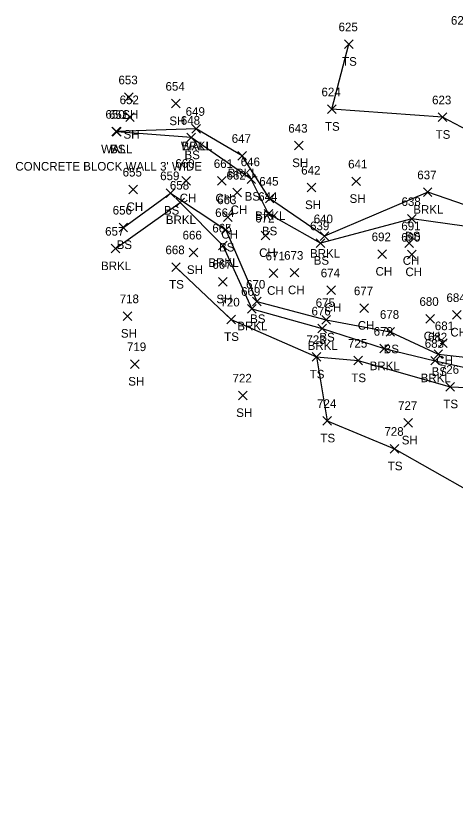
# Model space of a CAD drawing. Extents: x 1638705 to 1644019, y 630225 to 637423.
# Drawn here: x 1643714 to 1643815.9, y 636980.7 to 637165.6 of the extents above; entities that cross this region are included whole.
import ezdxf

# ---------------------------------------------------------------- set-up
doc = ezdxf.new("R2010")
doc.units = 0
for name, color, linetype in [('L_A', 7, 'Continuous'), ('L_C', 7, 'Continuous'), ('L_I', 7, 'Continuous'), ('L_TIC', 7, 'Continuous'), ('LAWE', 7, 'Continuous'), ('LELB', 7, 'Continuous'), ('LW', 7, 'Continuous')]:
    doc.layers.add(name, color=color, linetype=linetype)

msp = doc.modelspace()

# ---------------------------------------------------------------- linework, layer by layer
at = {"layer": 'L_TIC'}
for points in [[(1643790.25, 637158.07), (1643792.25, 637160.07)], [(1643792.25, 637158.07), (1643790.25, 637160.07)], [(1643739.18, 637145.77), (1643741.18, 637147.77)], [(1643741.18, 637145.77), (1643739.18, 637147.77)], [(1643750.1, 637144.29), (1643752.1, 637146.29)], [(1643752.1, 637144.29), (1643750.1, 637146.29)], [(1643786.29, 637142.99), (1643788.29, 637144.99)], [(1643788.29, 637142.99), (1643786.29, 637144.99)], [(1643739.45, 637141.16), (1643741.45, 637143.16)], [(1643741.45, 637141.16), (1643739.45, 637143.16)], [(1643811.95, 637141.13), (1643813.95, 637143.13)], [(1643813.95, 637141.13), (1643811.95, 637143.13)], [(1643736.25, 637137.79), (1643738.25, 637139.79)], [(1643738.25, 637137.79), (1643736.25, 637139.79)], [(1643736.4, 637137.75), (1643738.4, 637139.75)], [(1643738.4, 637137.75), (1643736.4, 637139.75)], [(1643754.78, 637138.46), (1643756.78, 637140.46)], [(1643756.78, 637138.46), (1643754.78, 637140.46)], [(1643754.78, 637138.46), (1643756.78, 637140.46)], [(1643756.78, 637138.46), (1643754.78, 637140.46)], [(1643753.65, 637136.4), (1643755.65, 637138.4)], [(1643755.65, 637136.4), (1643753.65, 637138.4)], [(1643778.59, 637134.56), (1643780.59, 637136.56)], [(1643780.59, 637134.56), (1643778.59, 637136.56)], [(1643765.46, 637132.19), (1643767.46, 637134.19)], [(1643767.46, 637132.19), (1643765.46, 637134.19)], [(1643752.5, 637126.41), (1643754.5, 637128.41)], [(1643754.5, 637126.41), (1643752.5, 637128.41)], [(1643767.6, 637126.78), (1643769.6, 637128.78)], [(1643769.6, 637126.78), (1643767.6, 637128.78)], [(1643760.78, 637126.36), (1643762.78, 637128.36)], [(1643762.78, 637126.36), (1643760.78, 637128.36)], [(1643781.58, 637124.82), (1643783.58, 637126.82)], [(1643783.58, 637124.82), (1643781.58, 637126.82)], [(1643791.9, 637126.26), (1643793.9, 637128.26)], [(1643793.9, 637126.26), (1643791.9, 637128.26)], [(1643740.15, 637124.38), (1643742.15, 637126.38)], [(1643742.15, 637124.38), (1643740.15, 637126.38)], [(1643748.87, 637123.53), (1643750.87, 637125.53)], [(1643750.87, 637123.53), (1643748.87, 637125.53)], [(1643764.3, 637123.67), (1643766.3, 637125.67)], [(1643766.3, 637123.67), (1643764.3, 637125.67)], [(1643808.52, 637123.74), (1643810.52, 637125.74)], [(1643810.52, 637123.74), (1643808.52, 637125.74)], [(1643751.11, 637121.35), (1643753.11, 637123.35)], [(1643753.11, 637121.35), (1643751.11, 637123.35)], [(1643771.85, 637122.27), (1643773.85, 637124.27)], [(1643773.85, 637122.27), (1643771.85, 637124.27)], [(1643762.14, 637117.97), (1643764.14, 637119.97)], [(1643764.14, 637117.97), (1643762.14, 637119.97)], [(1643771.61, 637118.73), (1643773.61, 637120.73)], [(1643773.61, 637118.73), (1643771.61, 637120.73)], [(1643804.86, 637117.55), (1643806.86, 637119.55)], [(1643806.86, 637117.55), (1643804.86, 637119.55)], [(1643737.9, 637115.56), (1643739.9, 637117.56)], [(1643739.9, 637115.56), (1643737.9, 637117.56)], [(1643761.67, 637114.99), (1643763.67, 637116.99)], [(1643763.67, 637114.99), (1643761.67, 637116.99)], [(1643770.92, 637113.71), (1643772.92, 637115.71)], [(1643772.92, 637113.71), (1643770.92, 637115.71)], [(1643784.58, 637113.55), (1643786.58, 637115.55)], [(1643786.58, 637113.55), (1643784.58, 637115.55)], [(1643783.63, 637111.92), (1643785.63, 637113.92)], [(1643785.63, 637111.92), (1643783.63, 637113.92)], [(1643783.63, 637111.92), (1643785.63, 637113.92)], [(1643785.63, 637111.92), (1643783.63, 637113.92)], [(1643804.25, 637111.9), (1643806.25, 637113.9)], [(1643806.25, 637111.9), (1643804.25, 637113.9)], [(1643736.09, 637110.66), (1643738.09, 637112.66)], [(1643738.09, 637110.66), (1643736.09, 637112.66)], [(1643754.16, 637109.78), (1643756.16, 637111.78)], [(1643756.16, 637109.78), (1643754.16, 637111.78)], [(1643761, 637111.4), (1643763, 637113.4)], [(1643763, 637111.4), (1643761, 637113.4)], [(1643797.93, 637109.38), (1643799.93, 637111.38)], [(1643799.93, 637109.38), (1643797.93, 637111.38)], [(1643804.87, 637109.27), (1643806.87, 637111.27)], [(1643806.87, 637109.27), (1643804.87, 637111.27)], [(1643750.12, 637106.36), (1643752.12, 637108.36)], [(1643752.12, 637106.36), (1643750.12, 637108.36)], [(1643772.77, 637104.94), (1643774.77, 637106.94)], [(1643774.77, 637104.94), (1643772.77, 637106.94)], [(1643777.62, 637105.08), (1643779.62, 637107.08)], [(1643779.62, 637105.08), (1643777.62, 637107.08)], [(1643761.01, 637102.98), (1643763.01, 637104.98)], [(1643763.01, 637102.98), (1643761.01, 637104.98)], [(1643786.12, 637101), (1643788.12, 637103)], [(1643788.12, 637101), (1643786.12, 637103)], [(1643768.88, 637098.38), (1643770.88, 637100.38)], [(1643770.88, 637098.38), (1643768.88, 637100.38)], [(1643793.81, 637096.85), (1643795.81, 637098.85)], [(1643795.81, 637096.85), (1643793.81, 637098.85)], [(1643738.85, 637095), (1643740.85, 637097)], [(1643740.85, 637095), (1643738.85, 637097)], [(1643767.69, 637096.71), (1643769.69, 637098.71)], [(1643769.69, 637096.71), (1643767.69, 637098.71)], [(1643815.29, 637095.27), (1643817.29, 637097.27)], [(1643817.29, 637095.27), (1643815.29, 637097.27)], [(1643762.89, 637094.24), (1643764.89, 637096.24)], [(1643764.89, 637094.24), (1643762.89, 637096.24)], [(1643784.95, 637094.12), (1643786.95, 637096.12)], [(1643786.95, 637094.12), (1643784.95, 637096.12)], [(1643809.11, 637094.38), (1643811.11, 637096.38)], [(1643811.11, 637094.38), (1643809.11, 637096.38)], [(1643784.02, 637092.15), (1643786.02, 637094.15)], [(1643786.02, 637092.15), (1643784.02, 637094.15)], [(1643799.85, 637091.37), (1643801.85, 637093.37)], [(1643801.85, 637091.37), (1643799.85, 637093.37)], [(1643812.02, 637088.74), (1643814.02, 637090.74)], [(1643814.02, 637088.74), (1643812.02, 637090.74)], [(1643798.41, 637087.46), (1643800.41, 637089.46)], [(1643800.41, 637087.46), (1643798.41, 637089.46)], [(1643810.99, 637086.14), (1643812.99, 637088.14)], [(1643812.99, 637086.14), (1643810.99, 637088.14)], [(1643740.54, 637083.88), (1643742.54, 637085.88)], [(1643742.54, 637083.88), (1643740.54, 637085.88)], [(1643782.74, 637085.53), (1643784.74, 637087.53)], [(1643784.74, 637085.53), (1643782.74, 637087.53)], [(1643782.74, 637085.53), (1643784.74, 637087.53)], [(1643784.74, 637085.53), (1643782.74, 637087.53)], [(1643792.4, 637084.68), (1643794.4, 637086.68)], [(1643794.4, 637084.68), (1643792.4, 637086.68)], [(1643810.25, 637084.66), (1643812.25, 637086.66)], [(1643812.25, 637084.66), (1643810.25, 637086.66)], [(1643813.75, 637078.62), (1643815.75, 637080.62)], [(1643815.75, 637078.62), (1643813.75, 637080.62)], [(1643765.6, 637076.6), (1643767.6, 637078.6)], [(1643767.6, 637076.6), (1643765.6, 637078.6)], [(1643785.22, 637070.71), (1643787.22, 637072.71)], [(1643787.22, 637070.71), (1643785.22, 637072.71)], [(1643804.01, 637070.24), (1643806.01, 637072.24)], [(1643806.01, 637070.24), (1643804.01, 637072.24)], [(1643800.85, 637064.24), (1643802.85, 637066.24)], [(1643802.85, 637064.24), (1643800.85, 637066.24)]]:
    msp.add_lwpolyline(points, dxfattribs=at)
at = {"layer": 'LAWE'}
for points in [[(1643849.23, 637088.49), (1643846.16, 637095.89), (1643839.09, 637105.62), (1643831.26, 637117.26), (1643809.52, 637124.74), (1643785.58, 637114.55), (1643772.85, 637123.27), (1643766.46, 637133.19), (1643755.78, 637139.46)], [(1643737.09, 637111.66), (1643752.11, 637122.35), (1643762, 637112.4), (1643768.69, 637097.71), (1643785.02, 637093.15), (1643799.41, 637088.46), (1643811.25, 637085.66), (1643826.85, 637082.12), (1643836.07, 637077.13), (1643839.82, 637076.93), (1643844.4, 637079.83)]]:
    msp.add_lwpolyline(points, dxfattribs=at)
at = {"layer": 'LELB'}
for points in [[(1643855.35, 637129.62), (1643833.54, 637131.3), (1643812.95, 637142.13), (1643787.29, 637143.99), (1643791.25, 637159.07)], [(1643784.63, 637112.92), (1643772.61, 637119.73), (1643768.6, 637127.78), (1643754.65, 637137.4), (1643737.4, 637138.75)], [(1643738.9, 637116.56), (1643749.87, 637124.53), (1643762.67, 637115.99), (1643769.88, 637099.38), (1643785.95, 637095.12), (1643800.85, 637092.37), (1643811.99, 637087.14), (1643823.88, 637085.88), (1643836.52, 637078.79), (1643843.54, 637079.59), (1643841.41, 637081.01), (1643842.47, 637084.34), (1643844.49, 637083.14), (1643845.69, 637086.32), (1643845.17, 637086.3), (1643846.99, 637088.33)], [(1643846.87, 637088.25), (1643845.01, 637094.84), (1643836.71, 637104.68), (1643830.65, 637115.1), (1643805.86, 637118.55), (1643784.63, 637112.92)], [(1643751.12, 637107.36), (1643763.89, 637095.24), (1643783.74, 637086.53), (1643793.4, 637085.68), (1643814.75, 637079.62), (1643828.43, 637079.03), (1643841.12, 637075.24), (1643849.88, 637074.96), (1643851.22, 637078.23), (1643848.74, 637082.34), (1643849.86, 637085.42), (1643854.35, 637085.98), (1643854.22, 637098.04)], [(1643783.74, 637086.53), (1643786.22, 637071.71), (1643801.85, 637065.24), (1643819.33, 637055.34), (1643834.95, 637042.42), (1643840.05, 637008.23), (1643832.85, 636980.73)]]:
    msp.add_lwpolyline(points, dxfattribs=at)
at = {"layer": 'LW'}
msp.add_lwpolyline([(1643755.78, 637139.46), (1643737.25, 637138.79)], dxfattribs=at)

# ---------------------------------------------------------------- texts
at = {"layer": 'L_A'}
for s, p in [('TS', (1643789.66, 637154.07)), ('SH', (1643738.67, 637141.77)), ('SH', (1643749.58, 637140.29)), ('TS', (1643785.69, 637138.99)), ('SH', (1643738.94, 637137.16)), ('TS', (1643811.36, 637137.13)), ('WALL', (1643733.74, 637133.79)), ('WALL', (1643752.26, 637134.46)), ('BRKL', (1643752.42, 637134.46)), ('BS', (1643735.84, 637133.75)), ('BS', (1643753.09, 637132.4)), ('SH', (1643778.08, 637130.56)), ('BRKL', (1643763.11, 637128.19)), ('BS', (1643767.04, 637122.78)), ('CH', (1643751.99, 637122.41)), ('CH', (1643760.27, 637122.36)), ('SH', (1643781.07, 637120.82)), ('SH', (1643791.39, 637122.26)), ('CH', (1643739.64, 637120.38)), ('BS', (1643748.31, 637119.53)), ('CH', (1643763.79, 637119.67)), ('BRKL', (1643806.17, 637119.74)), ('BRKL', (1643748.76, 637117.35)), ('BRKL', (1643769.5, 637118.27)), ('CH', (1643761.63, 637113.97)), ('BS', (1643771.05, 637114.73)), ('BS', (1643804.3, 637113.55)), ('BS', (1643737.34, 637111.56)), ('BS', (1643761.11, 637110.99)), ('CH', (1643770.41, 637109.71)), ('BRKL', (1643782.22, 637109.55)), ('BS', (1643783.07, 637107.92)), ('BS', (1643783.07, 637107.92)), ('CH', (1643803.74, 637107.9)), ('BRKL', (1643733.73, 637106.66)), ('BRKL', (1643758.65, 637107.4)), ('SH', (1643753.65, 637105.78)), ('CH', (1643797.42, 637105.38)), ('CH', (1643804.36, 637105.27)), ('TS', (1643749.53, 637102.36)), ('CH', (1643772.26, 637100.94)), ('CH', (1643777.1, 637101.08)), ('SH', (1643760.5, 637098.98)), ('CH', (1643785.61, 637097)), ('BS', (1643768.32, 637094.38)), ('BRKL', (1643765.34, 637092.71)), ('CH', (1643793.3, 637092.85)), ('CH', (1643814.78, 637091.27)), ('SH', (1643738.33, 637091)), ('TS', (1643762.3, 637090.24)), ('BS', (1643784.39, 637090.12)), ('CH', (1643808.6, 637090.38)), ('BRKL', (1643781.67, 637088.15)), ('BS', (1643799.29, 637087.37)), ('CH', (1643811.51, 637084.74)), ('BRKL', (1643796.06, 637083.46)), ('BS', (1643810.43, 637082.14)), ('TS', (1643782.15, 637081.53)), ('TS', (1643782.15, 637081.53)), ('TS', (1643791.81, 637080.68)), ('BRKL', (1643807.89, 637080.66)), ('SH', (1643740.03, 637079.88)), ('TS', (1643813.16, 637074.62)), ('SH', (1643765.09, 637072.6)), ('TS', (1643784.63, 637066.71)), ('SH', (1643803.5, 637066.24)), ('TS', (1643800.26, 637060.24))]:
    msp.add_text(s, height=2, dxfattribs=at).set_placement(p)
at = {"layer": 'L_C'}
msp.add_text("CONCRETE BLOCK WALL 3' WIDE", height=2, dxfattribs=at).set_placement((1643713.84, 637129.75))
at = {"layer": 'L_I'}
for s, p in [('626', (1643814.92, 637163.6)), ('625', (1643788.84, 637162.07)), ('653', (1643737.77, 637149.77)), ('654', (1643748.69, 637148.29)), ('624', (1643784.88, 637146.99)), ('652', (1643738.04, 637145.16)), ('623', (1643810.54, 637145.13)), ('650', (1643734.75, 637141.79)), ('651', (1643735.56, 637141.75)), ('649', (1643753.36, 637142.46)), ('649', (1643753.36, 637142.46)), ('648', (1643752.24, 637140.4)), ('643', (1643777.18, 637138.56)), ('647', (1643764.05, 637136.19)), ('660', (1643750.96, 637130.41)), ('661', (1643759.89, 637130.36)), ('646', (1643766.14, 637130.78)), ('641', (1643791.06, 637130.26)), ('655', (1643738.74, 637128.38)), ('642', (1643780.17, 637128.82)), ('659', (1643747.45, 637127.53)), ('662', (1643762.84, 637127.67)), ('637', (1643807.11, 637127.74)), ('658', (1643749.7, 637125.35)), ('645', (1643770.44, 637126.27)), ('644', (1643770.2, 637122.73)), ('663', (1643760.68, 637121.97)), ('638', (1643803.45, 637121.55)), ('656', (1643736.43, 637119.56)), ('664', (1643760.21, 637118.99)), ('672', (1643769.51, 637117.71)), ('640', (1643783.08, 637117.55)), ('665', (1643759.55, 637115.4)), ('639', (1643782.22, 637115.92)), ('639', (1643782.22, 637115.92)), ('691', (1643803.41, 637115.9)), ('657', (1643734.68, 637114.66)), ('666', (1643752.65, 637113.78)), ('692', (1643796.52, 637113.38)), ('690', (1643803.38, 637113.27)), ('668', (1643748.67, 637110.36)), ('671', (1643771.92, 637108.94)), ('673', (1643776.21, 637109.08)), ('667', (1643759.56, 637106.98)), ('674', (1643784.71, 637105)), ('670', (1643767.38, 637102.38)), ('669', (1643766.23, 637100.71)), ('677', (1643792.4, 637100.85)), ('718', (1643738.05, 637099)), ('684', (1643813.88, 637099.27)), ('720', (1643761.44, 637098.24)), ('675', (1643783.54, 637098.12)), ('680', (1643807.61, 637098.38)), ('676', (1643782.56, 637096.15)), ('678', (1643798.44, 637095.37)), ('679', (1643796.99, 637091.46)), ('681', (1643811.18, 637092.74)), ('723', (1643781.38, 637089.53)), ('723', (1643781.38, 637089.53)), ('682', (1643809.58, 637090.14)), ('719', (1643739.74, 637087.88)), ('725', (1643791.03, 637088.68)), ('683', (1643808.84, 637088.66)), ('726', (1643812.34, 637082.62)), ('722', (1643764.24, 637080.6)), ('724', (1643783.86, 637074.71)), ('727', (1643802.65, 637074.24)), ('728', (1643799.48, 637068.24))]:
    msp.add_text(s, height=2, dxfattribs=at).set_placement(p)

doc.saveas('drawing.dxf')
